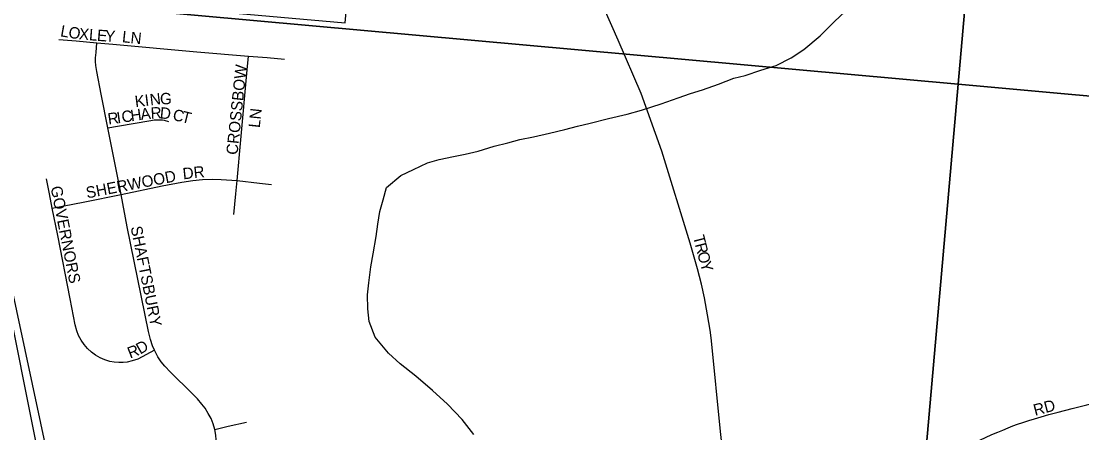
# Model space of a CAD drawing. Extents: x 0 to 680, y 0 to 440.
# Drawn here: x 491.37 to 506.93, y 352.33 to 358.36 of the extents above; entities that cross this region are included whole.
import ezdxf

# ---------------------------------------------------------------- set-up
doc = ezdxf.new("R2010")
doc.units = 0
for name, color, linetype in [('GM_X_City_Street', 7, 'Continuous'), ('GM_X_City_Street_Text', 7, 'Continuous'), ('GM_X_Corporation', 7, 'Continuous'), ('GM_X_Minor_River', 7, 'Continuous'), ('GM_X_Rail_Line', 7, 'Continuous'), ('GM_X_Section', 7, 'Continuous')]:
    doc.layers.add(name, color=color, linetype=linetype)

msp = doc.modelspace()

# ---------------------------------------------------------------- linework, layer by layer
at = {"layer": 'GM_X_City_Street'}
for points in [[(500.126, 358.086), (499.812, 358.809), (499.279, 359.997), (499.251, 360.056), (499.182, 360.19), (499.181, 360.194)], [(491.923, 358.099), (492.179, 358.077), (492.481, 358.049)], [(492.641, 356.8), (492.545, 357.295), (492.481, 357.63), (492.467, 357.714), (492.462, 357.773), (492.462, 357.827), (492.469, 357.908), (492.481, 358.049)], [(492.481, 358.049), (492.717, 358.028), (493.949, 357.918), (494.705, 357.855)], [(501.794, 350.402), (501.789, 350.522), (501.767, 350.959), (501.765, 350.981), (501.761, 351.024), (501.722, 351.482), (501.626, 352.397), (501.502, 353.628), (501.491, 353.723), (501.476, 353.833), (501.44, 354.06), (501.394, 354.307), (501.349, 354.51), (501.292, 354.732), (501.183, 355.11), (500.77, 356.46), (500.467, 357.304), (500.126, 358.086)], [(494.538, 356.028), (494.594, 356.624), (494.686, 357.65), (494.705, 357.855)], [(494.705, 357.855), (494.98, 357.832), (495.235, 357.81)], [(492.641, 356.8), (492.784, 356.825), (493.273, 356.911), (493.32, 356.917), (493.36, 356.921), (493.415, 356.921), (493.444, 356.919), (493.469, 356.915), (493.533, 356.897)], [(492.835, 355.825), (492.713, 356.436), (492.641, 356.8)], [(491.827, 355.622), (491.784, 355.835), (491.741, 356.052)], [(492.835, 355.825), (493.437, 355.949), (493.727, 356.006), (493.89, 356.03), (494.031, 356.043), (494.174, 356.048), (494.305, 356.045), (494.538, 356.028)], [(494.489, 355.533), (494.518, 355.834), (494.538, 356.028)], [(494.538, 356.028), (494.866, 355.99), (495.043, 355.969)], [(491.827, 355.622), (492.304, 355.717), (492.835, 355.825)], [(493.324, 353.541), (493.297, 353.604), (493.266, 353.697), (493.237, 353.814), (492.926, 355.35), (492.835, 355.825)], [(493.324, 353.541), (493.081, 353.412), (492.997, 353.386), (492.923, 353.368), (492.868, 353.361), (492.803, 353.359), (492.737, 353.365), (492.672, 353.377), (492.599, 353.399), (492.528, 353.429), (492.462, 353.467), (492.4, 353.513), (492.345, 353.566), (492.295, 353.624), (492.251, 353.687), (492.214, 353.755), (492.186, 353.826), (492.163, 353.911), (492.088, 354.296), (491.906, 355.223), (491.827, 355.622)], [(494.21, 352.381), (494.187, 352.462), (494.157, 352.538), (494.114, 352.615), (494.068, 352.69), (494.023, 352.751), (493.959, 352.826), (493.876, 352.913), (493.56, 353.217), (493.477, 353.305), (493.422, 353.373), (493.374, 353.446), (493.324, 353.541)], [(505.113, 352.07), (505.166, 352.096), (505.265, 352.142), (505.378, 352.196), (505.515, 352.261), (505.611, 352.303), (505.696, 352.339), (505.769, 352.371), (505.847, 352.403), (505.918, 352.43), (505.986, 352.455), (506.064, 352.482), (506.152, 352.511), (506.236, 352.537), (506.333, 352.566), (506.446, 352.598), (506.581, 352.634), (506.788, 352.687), (507.005, 352.742), (507.414, 352.849), (507.475, 352.865), (507.749, 352.935), (508.065, 353.017)], [(494.175, 351.39), (494.23, 352.019), (494.236, 352.139), (494.233, 352.227), (494.227, 352.295), (494.21, 352.381)], [(494.21, 352.381), (494.409, 352.429), (494.674, 352.488)]]:
    msp.add_lwpolyline(points, dxfattribs=at)
at = {"layer": 'GM_X_Corporation'}
msp.add_lwpolyline([(487.404, 359.153), (486.745, 351.206), (488.722, 351.066), (488.754, 351.326), (491.399, 351.133), (492.493, 345.531), (492.398, 345.125), (493.029, 345.299), (491.765, 351.97), (490.292, 358.857), (496.122, 358.339), (496.284, 360.123)], dxfattribs=at)
at = {"layer": 'GM_X_Minor_River'}
msp.add_lwpolyline([(498.009, 352.306), (497.84, 352.524), (497.625, 352.75), (497.402, 352.949), (497.16, 353.162), (496.93, 353.341), (496.76, 353.499), (496.564, 353.731), (496.476, 353.96), (496.454, 354.148), (496.452, 354.355), (496.469, 354.529), (496.502, 354.762), (496.533, 354.956), (496.579, 355.209), (496.603, 355.389), (496.634, 355.575), (496.679, 355.748), (496.73, 355.928), (496.941, 356.104), (497.124, 356.193), (497.333, 356.289), (497.502, 356.338), (497.71, 356.38), (497.885, 356.416), (498.073, 356.459), (498.309, 356.534), (498.511, 356.583), (498.686, 356.632), (498.887, 356.668), (499.123, 356.723), (499.345, 356.778), (499.533, 356.827), (499.715, 356.87), (499.984, 356.937), (500.26, 357.004), (500.468, 357.06), (500.758, 357.153), (501.008, 357.241), (501.19, 357.304), (501.365, 357.36), (501.601, 357.442), (501.824, 357.531), (501.992, 357.567), (502.221, 357.649), (502.444, 357.717), (502.667, 357.826), (502.85, 357.949), (503.089, 358.151), (503.301, 358.36), (503.534, 358.582)], dxfattribs=at)
at = {"layer": 'GM_X_Rail_Line'}
msp.add_lwpolyline([(485.947, 380.403), (486.206, 379.104), (486.637, 376.926), (487.969, 370.267), (489.037, 364.928), (489.57, 362.264), (491.252, 353.849), (492.398, 348.107), (493.092, 344.622), (494.169, 339.255)], dxfattribs=at)
at = {"layer": 'GM_X_Section'}
for points in [[(489.121, 376.587), (506.667, 375.043), (505.116, 357.444), (487.63, 359.026)], [(506.667, 375.043), (524.357, 373.718), (522.674, 355.848), (505.116, 357.444)], [(505.116, 357.444), (503.581, 339.978), (485.85, 341.665), (487.63, 359.026)], [(522.674, 355.848), (521.179, 338.368), (503.581, 339.978), (505.116, 357.444)]]:
    msp.add_lwpolyline(points, close=True, dxfattribs=at)

# ---------------------------------------------------------------- texts
at = {"layer": 'GM_X_City_Street_Text'}
for s, height, rotation, p in [('L', 0.167, 350.0886, (491.937, 358.145)), ('O', 0.167, 351.2161, (492.056, 358.125)), ('X', 0.167, 354.8349, (492.212, 358.101)), ('L', 0.167, 355.4303, (492.361, 358.087)), ('E', 0.167, 355.4303, (492.478, 358.078)), ('Y', 0.167, 355.9615, (492.597, 358.069)), ('LN', 0.1669, 353.9934, (492.845, 358.058)), ('CROSSBOW', 0.1669, 83.9914, (494.543, 356.4)), ('K', 0.167, 7.0545, (493.048, 357.103)), ('I', 0.167, 7.0626, (493.194, 357.121)), ('N', 0.167, 6.8133, (493.267, 357.13)), ('G', 0.167, 0, (493.407, 357.147)), ('C', 0.167, 8.137, (492.855, 356.877)), ('H', 0.167, 8.1363, (492.986, 356.896)), ('A', 0.167, 7.3202, (493.131, 356.916)), ('R', 0.167, 2.5993, (493.273, 356.935)), ('D', 0.167, 354.2633, (493.399, 356.941)), ('C', 0.167, 346.918, (493.583, 356.919)), ('T', 0.167, 346.0367, (493.711, 356.89)), ('LN', 0.1669, 83.9946, (494.87, 356.796)), ('R', 0.167, 8.137, (492.652, 356.848)), ('I', 0.167, 8.1502, (492.783, 356.866)), ('SHERWOOD', 0.1669, 10.885, (492.338, 355.766)), ('DR', 0.1669, 6.0114, (493.748, 356.046)), ('GOVERNORS', 0.1669, 281.1807, (491.801, 355.932)), ('SHAFTSBURY', 0.1669, 281.4322, (492.975, 355.345)), ('T', 0.167, 284.5002, (501.224, 355.206)), ('R', 0.167, 284.484, (501.253, 355.092)), ('O', 0.167, 284.5533, (501.286, 354.964)), ('Y', 0.167, 286.5829, (501.325, 354.816)), ('D', 0.167, 29.8531, (493.116, 353.476)), ('R', 0.167, 21.2782, (492.969, 353.417)), ('RD', 0.1669, 14.7458, (506.243, 352.579))]:
    msp.add_text(s, height=height, rotation=rotation, dxfattribs=at).set_placement(p)

doc.saveas('drawing.dxf')
